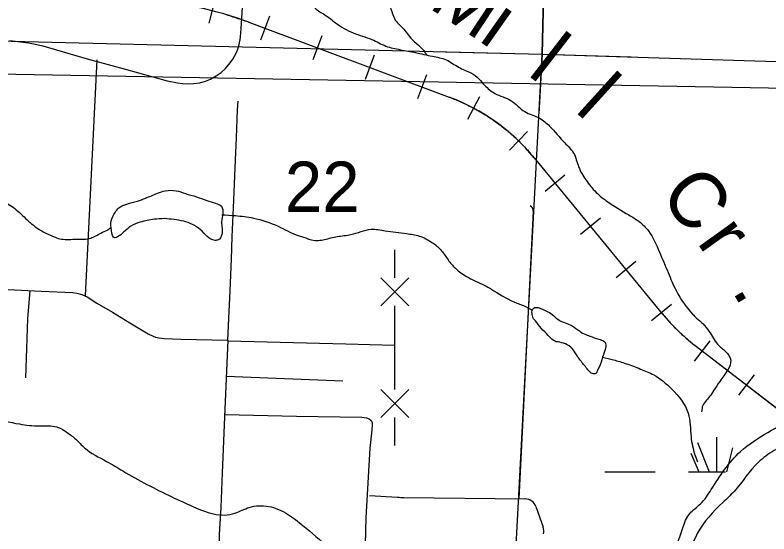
# Model space of a CAD drawing. Extents: x 1219626 to 1426462, y 456797 to 752399.
# Drawn here: x 1327316 to 1334060, y 638144 to 642787 of the extents above; entities that cross this region are included whole.
import ezdxf

# ---------------------------------------------------------------- set-up
doc = ezdxf.new("R2010")
doc.units = 0
for name, color, linetype in [('County Routes Highway Center Lines', 7, 'Continuous'), ('Lakes and Ponds', 7, 'Continuous'), ('Local Roads Improved', 7, 'Continuous'), ('Local Roads Paved', 7, 'Continuous'), ('Masks', 7, 'Continuous'), ('Narrow River Creek and Branch and Slough', 7, 'Continuous'), ('Narrow River Creek and Branch and Slough Text', 7, 'Continuous'), ('Quad Borders', 7, 'Continuous'), ('Railroads', 7, 'Continuous'), ('Section Lines', 7, 'Continuous'), ('Section Numbers', 7, 'Continuous'), ('Swamps', 7, 'Continuous')]:
    doc.layers.add(name, color=color, linetype=linetype)

msp = doc.modelspace()

# ---------------------------------------------------------------- linework, layer by layer
at = {"layer": 'County Routes Highway Center Lines'}
msp.add_lwpolyline([(1327269.2, 642558.3), (1327437, 642536.9), (1327493.8, 642527.7), (1327564.6, 642512.2), (1327960.5, 642393.8), (1328291.3, 642305), (1328676.5, 642199.3), (1328768.2, 642179.9), (1328813.3, 642174.6), (1328868.6, 642171.6), (1328911.3, 642173.1), (1328969, 642181.8), (1329020.5, 642195.9), (1329063.2, 642214.3), (1329113.6, 642242.5), (1329159.2, 642274), (1329199.5, 642308.4), (1329240.7, 642358.4), (1329264.5, 642391.4), (1329293.6, 642445.2), (1329309.1, 642482.1), (1329320.8, 642524.8), (1329327.1, 642554.9), (1329330.5, 642566), (1329333.4, 642592.7), (1329339.7, 642663.6), (1329351.3, 642858.6)], dxfattribs=at)
at = {"layer": 'Lakes and Ponds'}
for points in [[(1337496.8, 643358.7), (1337429, 643264.9), (1337335.2, 643134.4), (1337262.2, 642951.9), (1337173.5, 642738), (1337131.8, 642685.8), (1336725.2, 642425), (1336422.8, 642247.7), (1336244.5, 642121.7), (1336145.4, 641996.5), (1336072.4, 641923.4), (1335957.7, 641850.4), (1335832.6, 641667.8), (1335764.8, 641490.5), (1335698.1, 641245.8), (1335658, 640924.7), (1335603.2, 640640.2), (1335587.6, 640316.8), (1335629.3, 640069.1), (1335665.8, 639949.1), (1335697.1, 639787.4), (1335676.2, 639683.1), (1335551.1, 639484.9), (1335264.3, 639276.2), (1335123.6, 639177.1), (1334925.5, 639119.7), (1334539.7, 639041.5), (1334273.8, 638978.9), (1334106.9, 638890.2), (1333966.2, 638785.9), (1333748.1, 638523.6), (1333648.1, 638426), (1333419.8, 638147.9), (1333325.9, 637908), (1333299.9, 637746.3), (1333378.1, 637600.2), (1333491.3, 637552.1), (1333576.2, 637506.3), (1333696.1, 637428.1), (1333727.4, 637188.1), (1333706.5, 637010.7), (1333654.4, 636781.2), (1333670, 636666.5), (1333774.3, 636520.4), (1333836.9, 636452.6), (1333899.4, 636379.6), (1333935.9, 636207.4), (1333920.3, 636009.2), (1333826.4, 635816.2), (1333779.5, 635596.2), (1333717, 635513.6), (1333587.6, 635343.8), (1333482.4, 635210.2), (1333477.1, 635079.8), (1333461.5, 634876.3), (1333435.4, 634740.7), (1333338.8, 634540.9), (1333258.6, 634436.5), (1333232.1, 634325.7), (1333338.8, 634324.1), (1333466.7, 634292.1), (1333591.8, 634210.9), (1333701.3, 633877.1), (1333664.8, 633715.4), (1333628.3, 633621.5), (1333498, 633556.6), (1333425, 633447), (1333372.9, 633347.9), (1333284.2, 633207.1), (1333294.7, 633026.8), (1333419.1, 632991.3), (1333499.3, 633039.4), (1333675.3, 633089.4), (1333717, 633073.7), (1333847.3, 632880.7), (1333828.3, 632750.4), (1333701.3, 632515.6), (1333563.5, 632348.9), (1333477.1, 632275.6), (1333331.2, 632055), (1333284.2, 631940.2), (1333290.7, 631827), (1333379, 631618.3), (1333451.2, 631465.7), (1333440.6, 631340.3), (1333482.4, 631152.5), (1333482.4, 631079.5), (1333456.3, 630985.6), (1333362.9, 630919.8), (1333310.3, 630923), (1333190.4, 631001.3)], [(1332856.7, 631063.9), (1332789.9, 631132.1), (1332701.7, 631244.5), (1332685.6, 631381), (1332709.7, 631485.3), (1332798, 631565.6), (1332886.2, 631605.8), (1332998.6, 631637.9), (1333119, 631589.7), (1333195.6, 631533.3), (1333183.2, 631621.8), (1333133, 631710.7), (1333117.4, 631862), (1333159.1, 632081.1), (1333273.8, 632265.2), (1333375.8, 632392.6), (1333488.1, 632521.1), (1333633.5, 632672.1), (1333649.2, 632755.5), (1333659.6, 632823.4), (1333623.1, 632891.2), (1333508.4, 632859.9), (1333315.5, 632805.4), (1333180, 632826.3), (1333075.7, 632988), (1333075.7, 633066.2), (1333122.6, 633248.8), (1333153.9, 633316.6), (1333247.7, 633462.7), (1333325.9, 633640), (1333414.6, 633723.5), (1333461.5, 633754.8), (1333498, 633916.5), (1333472, 634025.9), (1333331.2, 634153.5), (1333211.3, 634127.4), (1333112.2, 634137.9), (1333014.6, 634218.6), (1332961, 634328.6), (1332990.6, 634459.4), (1333030.7, 634531.7), (1333038.7, 634612), (1333117.4, 634594.6), (1333180, 634678.1), (1333221.7, 634735.5), (1333284.2, 634865.9), (1333310.3, 635043.2), (1333352, 635236.2), (1333456, 635422.9), (1333571, 635617), (1333670, 635863.1), (1333696.7, 636049.2), (1333732.6, 636249.2), (1333664.6, 636358.6), (1333571, 636457.8), (1333503.2, 636645.6), (1333508.4, 636749.9), (1333544.9, 636963.8), (1333571, 637115.1), (1333581.4, 637287.2), (1333529.3, 637355), (1333456.3, 637381.1), (1333315.5, 637480.2), (1333237.3, 637506.3), (1333164.3, 637615.9), (1333138.3, 637746.3), (1333138.3, 637881.9), (1333237.3, 638059.2), (1333351.7, 638325.7), (1333450, 638415.5), (1333543.9, 638540.7), (1333805.1, 638881.4), (1334049.6, 639051.9), (1334336.3, 639187.6), (1334670, 639250.1), (1335019.3, 639333.6), (1335347.8, 639547.5), (1335499, 639870.9), (1335467.7, 640024.7), (1335431.2, 640337.7), (1335431.2, 640593.3), (1335467.7, 640968.8), (1335514.6, 641250.5), (1335587.6, 641480), (1335676.2, 641709.6), (1335811.2, 641956.5), (1336011.9, 642149.2), (1336284.3, 642356.5), (1336443.6, 642451.1), (1336683.5, 642545), (1336839.9, 642644.1)], [(1328411.1, 641122.1), (1328481.3, 641148.2), (1328589.6, 641192.3), (1328659.8, 641214.4), (1328758.1, 641214.4), (1328840.3, 641190.3), (1328938.6, 641160.2), (1329030.9, 641128.1), (1329109.1, 641104), (1329161.3, 641075.9), (1329163.3, 640935.4), (1329165.3, 640823), (1329133.2, 640774.9), (1329105.1, 640770.9), (1328972.7, 640867.2), (1328824.3, 640941.5), (1328649.8, 640965.5)], [(1328649.8, 640965.5), (1328561.5, 640959.5), (1328435.2, 640933.4), (1328350.9, 640897.3), (1328286.7, 640843.1), (1328232.6, 640801), (1328208.5, 640792.9), (1328178.4, 640859.2), (1328176.4, 640945.5), (1328210.5, 641019.7), (1328244.6, 641061.9), (1328316.8, 641096), (1328411.1, 641122.1)], [(1332157.8, 639864.4), (1332128.9, 639877.9), (1332086.4, 639920.3), (1332022.8, 639984), (1331970.7, 640051.6), (1331951.4, 640074.8), (1331941.7, 640117.2), (1331941.7, 640142.3), (1331966.8, 640169.3), (1331995.8, 640169.3), (1332034.3, 640153.9), (1332082.6, 640132.7), (1332132.7, 640097.9)], [(1332132.7, 640097.9), (1332184.8, 640055.5), (1332223.4, 640038.1), (1332281.3, 640014.9), (1332350.7, 639970.5), (1332408.6, 639933.9), (1332458.7, 639914.6), (1332537.8, 639885.6), (1332584.1, 639868.2), (1332599.5, 639848.9), (1332593.8, 639793), (1332572.5, 639725.4), (1332541.7, 639636.6), (1332520.5, 639594.2), (1332512.7, 639580.7), (1332479.9, 639578.7), (1332449.1, 639603.8), (1332387.4, 639679.1), (1332331.4, 639756.3), (1332287, 639816.1), (1332221.5, 639850.9), (1332157.8, 639864.4)]]:
    msp.add_spline(points, degree=3, dxfattribs=at)
at = {"layer": 'Local Roads Improved'}
for p, q in [((1331951.2, 641033.5), (1331824, 638458)), ((1330714.1, 640436.1), (1330714.1, 640686.1)), ((1330589.1, 640186.1), (1330839.1, 640436.1)), ((1330589.1, 640436.1), (1330839.1, 640186.1)), ((1330714.1, 639436.1), (1330714.1, 640186.1)), ((1330589.1, 639186.1), (1330839.1, 639436.1)), ((1330589.1, 639436.1), (1330839.1, 639186.1)), ((1330714.1, 638936.1), (1330714.1, 639186.1)), ((1330488.1, 638488), (1330738.3, 638472.9)), ((1331974.4, 638390.6), (1332040.1, 638204.7))]:
    msp.add_line(p, q, dxfattribs=at)
for points in [[(1329219.2, 639877.2), (1329192.9, 639260.2), (1329167.9, 638691.5), (1329156.7, 638380.9), (1329140.4, 638138.3), (1329133.5, 637682.3), (1329110.3, 637187.6), (1329078.4, 636599.1), (1329061.2, 636055.4), (1329041.4, 635492.7), (1329021.6, 634953.3), (1329000.1, 634404.4), (1328986.4, 634104.2), (1328980.4, 634068.9), (1328958.8, 634038.8), (1328936.5, 634029.3), (1328885.7, 634029.3), (1328724.8, 634030.2), (1327837, 634027.6), (1327513.5, 634029.3)], [(1329218.9, 639870.7), (1330274.3, 639844.4), (1330711.4, 639834)], [(1330795.3, 638470.9), (1331881.4, 638457.3)]]:
    msp.add_lwpolyline(points, dxfattribs=at)
for centre, radius, start, end in [((1331901.3, 641036), 50, 357.1714, 62.37816), ((1330810.3, 639670.8), 1200, 266.55966, 269.28384), ((1331880.1, 638357.3), 100, 19.44601, 89.28384), ((1331945.8, 638171.4), 100, 344.22182, 19.44601)]:
    msp.add_arc(centre, radius, start, end, dxfattribs=at)
at = {"layer": 'Local Roads Paved'}
for p, q in [((1328047.3, 642385.6), (1327942.9, 640274)), ((1329205.4, 639554.7), (1330247.1, 639515.4))]:
    msp.add_line(p, q, dxfattribs=at)
for points in [[(1329219.2, 639877.2), (1329226.8, 640071.5), (1329238.9, 640320.6), (1329251.4, 640603.2), (1329259.1, 640801.5), (1329274.2, 641130.1), (1329285.3, 641423.1), (1329295.7, 641687.6), (1329306.9, 641939.3), (1329311.6, 642016.7)], [(1326954.2, 640345.9), (1327547.5, 640315.4), (1327833.5, 640302.9), (1327867.9, 640299.5), (1327911.8, 640287), (1327961.3, 640266.4), (1328046.9, 640210), (1328187.1, 640128.7), (1328343.3, 640032.3), (1328505.9, 639935.6), (1328551.5, 639912.3), (1328572.6, 639904.6), (1328603.1, 639898.1), (1328648.7, 639891.7), (1328798.4, 639886.9), (1329219.2, 639877.2)], [(1327446.3, 640320.6), (1327425.3, 640070.6), (1327418, 639803.5), (1327408.9, 639542)], [(1329190.8, 639212.5), (1329834.7, 639199.1), (1330418.8, 639187.9), (1330460.1, 639181.9), (1330484.2, 639173.3), (1330502.3, 639159.5), (1330509.2, 639141.5), (1330510.9, 639114.8), (1330503.2, 639046.8), (1330491.1, 638912.6), (1330455, 638288.9), (1330446.4, 638054), (1330416.3, 637606.6), (1330412, 637534.3), (1330405.9, 637505.1), (1330385.3, 637490.5), (1330363.8, 637483.6), (1329893.2, 637500.8), (1329597.2, 637511.1), (1329126, 637522.2)]]:
    msp.add_lwpolyline(points, dxfattribs=at)
at = {"layer": 'Masks'}
for p, q in [((1332043.9, 642962.3), (1332030.5, 642436.6)), ((1331167.5, 642457.7), (1332030.5, 642436.6)), ((1332030.5, 642436.6), (1332002.5, 641904.4)), ((1332030.5, 642436.6), (1332828.9, 642412))]:
    msp.add_line(p, q, dxfattribs=at)
at = {"layer": 'Narrow River Creek and Branch and Slough'}
for points in [[(1327523.7, 647493.8), (1327491.2, 647422.2), (1327432.6, 647298.4), (1327426.1, 647200.7), (1327452.1, 647031.3), (1327497.7, 646842.4), (1327517.2, 646647), (1327549.8, 646497.2), (1327569.3, 646425.5), (1327601.9, 646373.4), (1327653.9, 646269.2), (1327719, 646112.8), (1327784.1, 645930.4), (1327855.8, 645748), (1327849.3, 645689.4), (1327940.4, 645546.1), (1327973, 645494), (1328018.5, 645448.4), (1328070.6, 645409.3), (1328122.7, 645272.5), (1328187.8, 645155.3), (1328246.4, 645096.6), (1328285.5, 645025), (1328265.9, 644933.8), (1328331, 644829.6), (1328370.1, 644757.9), (1328487.3, 644686.3), (1328598, 644634.1), (1328682.6, 644569), (1328773.7, 644471.3), (1328877.9, 644347.5), (1328923.5, 644236.8), (1328982.1, 644132.6), (1329021.1, 643969.7), (1329053.7, 643859), (1329053.7, 643780.8), (1329086.2, 643702.6), (1329190.4, 643624.5), (1329265.3, 643551.9), (1329382.5, 643428.1), (1329558.3, 643232.7), (1329668.9, 643141.5), (1329786.1, 643069.8), (1329890.3, 642998.2), (1329948.9, 642926.5), (1330001, 642848.4), (1330085.6, 642789.7), (1330183.3, 642718.1), (1330339.5, 642626.9), (1330508.8, 642568.3), (1330632.5, 642509.6), (1330762.7, 642477.1), (1330899.4, 642451), (1331049.2, 642418.4), (1331172.9, 642385.9), (1331283.5, 642320.7), (1331394.2, 642268.6), (1331465.8, 642216.5), (1331517.9, 642157.9), (1331609.1, 642086.2), (1331752.3, 642021.1), (1331876, 641923.4), (1332006.2, 641864.7), (1332097.4, 641793.1), (1332234.1, 641643.3), (1332312.2, 641552.1), (1332357.8, 641428.3), (1332422.9, 641311), (1332514, 641200.3), (1332618.2, 641115.6), (1332807, 640998.4), (1332898.1, 640939.7), (1332982.8, 640855.1), (1333080.4, 640666.2), (1333158.6, 640483.8), (1333230.2, 640320.9), (1333379.9, 640108.5), (1333412.5, 640075.9), (1333471.1, 640023.8), (1333523.2, 639958.7), (1333562.2, 639900), (1333601.3, 639841.4), (1333672.9, 639776.3), (1333718.5, 639698.1), (1333692.4, 639613.4), (1333620.8, 639509.2), (1333568.7, 639431), (1333529.7, 639372.4), (1333464.6, 639281.2), (1333458, 639235.6)], [(1330201.5, 644287.7), (1330270, 644204.7), (1330349.3, 644085.7), (1330425, 643898.2), (1330443, 643790), (1330468.2, 643624.1), (1330504.3, 643375.2), (1330518.7, 643194.9), (1330525.9, 643093.9), (1330572.7, 643011), (1330612.4, 642946), (1330677.3, 642841.4), (1330709.7, 642754.9), (1330792.6, 642661.1), (1330879.1, 642556.5), (1330962, 642480.8), (1330997.2, 642430)], [(1325238.9, 641414.7), (1325315.8, 641400.8), (1325487.3, 641378.2), (1325636.3, 641346.6), (1325816.8, 641328.5), (1325934.1, 641310.5), (1326037.9, 641296.9), (1326128.2, 641315), (1326295.2, 641364.7), (1326471.2, 641369.2), (1326674.3, 641351.1), (1326845.8, 641296.9), (1327035.3, 641206.6), (1327175.2, 641138.9), (1327297.1, 641066.6), (1327409.9, 640967.3), (1327518.2, 640877), (1327617.5, 640822.8), (1327730.4, 640782.2), (1327865.8, 640782.2), (1327992.1, 640791.2), (1328082.4, 640836.3), (1328141.1, 640863.4), (1328171.8, 640885.8)], [(1329164.3, 641000.7), (1329286.8, 640992), (1329447.4, 640970.3), (1329668.7, 640896.5), (1329838, 640818.3), (1329916.1, 640792.3), (1329968.2, 640774.9), (1330085.4, 640779.2), (1330198.2, 640805.3), (1330319.8, 640822.7), (1330502.1, 640870.4), (1330627.9, 640857.4), (1330818.9, 640831.4), (1330931.8, 640809.6), (1331044.6, 640753.2), (1331122.7, 640688), (1331183.5, 640605.5), (1331244.3, 640531.7), (1331344.1, 640453.5), (1331435.2, 640405.8), (1331513.4, 640371), (1331600.2, 640318.9), (1331804.2, 640210.3), (1331899.6, 640171.3), (1331943.4, 640146.9)], [(1332572.2, 639724.5), (1332669.2, 639702.2), (1332782, 639667.5), (1332912.2, 639619.7), (1333029.4, 639567.6), (1333190, 639441.7), (1333337.6, 639224.5), (1333363.6, 639011.8), (1333398.4, 638851.1), (1333420.1, 638790.3)], [(1324055.1, 638887.8), (1324123.7, 638999.2), (1324218, 639093.5), (1324355.1, 639256.5), (1324440.8, 639350.8), (1324526.5, 639436.5), (1324612.2, 639470.8), (1324715, 639470.8), (1324929.3, 639462.3), (1325074.9, 639453.7), (1325246.3, 639479.4), (1325434.9, 639548), (1325640.6, 639599.4), (1325777.7, 639625.2), (1325914.8, 639659.5), (1326129, 639650.9), (1326283.3, 639599.4), (1326463.2, 639556.6), (1326548.9, 639505.1), (1326643.2, 639436.5), (1326711.8, 639350.8), (1326806, 639265), (1326926, 639213.6), (1327097.4, 639179.3), (1327354.5, 639127.8), (1327534.5, 639110.7), (1327688.7, 639102.1), (1327783, 639050.7), (1327860.1, 638990.7), (1327937.2, 638913.5), (1328134.3, 638793.4), (1328280, 638707.7), (1328494.3, 638587.7), (1328717.1, 638476.2), (1328905.6, 638390.4), (1329188.4, 638313.3), (1329282.7, 638330.4), (1329411.2, 638381.9), (1329582.6, 638390.4), (1329754, 638321.9), (1329891.1, 638219), (1330118.3, 638021.7), (1330229.7, 637910.3), (1330358.2, 637798.8), (1330495.3, 637738.8), (1330649.6, 637653), (1330821, 637550.2), (1330906.7, 637464.4), (1330992.4, 637344.4), (1331095.2, 637207.2), (1331172.3, 637087.1), (1331206.6, 636992.8), (1331283.7, 636872.8), (1331378, 636761.3), (1331438, 636658.4), (1331489.4, 636555.5), (1331523.7, 636478.3), (1331532.3, 636418.3), (1331540.8, 636332.6), (1331566.5, 636204), (1331626.5, 636092.5), (1331763.6, 635989.6), (1331969.3, 635912.4)]]:
    msp.add_spline(points, degree=3, dxfattribs=at)
at = {"layer": 'Quad Borders'}
msp.add_line((1340252.6, 642021.5), (1300989.8, 642732), dxfattribs=at)
at = {"layer": 'Railroads'}
for p, q in [((1329104.3, 642937.6), (1329047.9, 642714.6)), ((1329408.4, 642722.1), (1331200.3, 642052.2)), ((1329590.7, 642776.8), (1329510.2, 642561.3)), ((1330059, 642601.7), (1329978.5, 642386.2)), ((1330527.4, 642426.6), (1330446.8, 642211.1)), ((1330995.7, 642251.5), (1330915.2, 642036)), ((1331471.5, 642055.7), (1331363.7, 641852.5)), ((1331900.4, 641743.5), (1331740.7, 641578)), ((1331960.6, 641509), (1333106.7, 640114.4)), ((1332235.7, 641355.4), (1332058, 641209.3)), ((1332553.2, 640969.1), (1332375.5, 640823)), ((1332870.6, 640582.8), (1332692.9, 640436.8)), ((1333188.1, 640196.5), (1333010.4, 640050.5)), ((1333532.8, 639873.3), (1333392.5, 639691)), ((1333399.5, 639830.8), (1335090.4, 638529.3)), ((1333929, 639568.3), (1333788.8, 639386.1))]:
    msp.add_line(p, q, dxfattribs=at)
for points in [[(1329202.8, 642791.1), (1329218.1, 642786.5), (1329233.4, 642781.8), (1329248.7, 642777.1), (1329264, 642772.2), (1329279.2, 642767.3), (1329294.4, 642762.3), (1329309.6, 642757.2), (1329324.7, 642752.1), (1329339.8, 642746.9), (1329354.9, 642741.6), (1329370, 642736.2), (1329385.1, 642730.8), (1329400.1, 642725.2), (1329408.4, 642722.1), (1331200.3, 642052.2), (1331211.5, 642048), (1331222.7, 642043.7), (1331233.9, 642039.3), (1331245, 642034.8), (1331256.1, 642030.3), (1331267.2, 642025.7), (1331278.2, 642021), (1331289.2, 642016.2), (1331300.2, 642011.4), (1331311.2, 642006.5), (1331322.1, 642001.5), (1331333, 641996.5), (1331343.8, 641991.3), (1331354.7, 641986.1), (1331365.4, 641980.9), (1331376.2, 641975.5), (1331386.9, 641970.1), (1331397.6, 641964.6), (1331408.2, 641959.1), (1331418.8, 641953.5), (1331429.4, 641947.8), (1331439.9, 641942), (1331450.4, 641936.2), (1331460.8, 641930.3), (1331471.2, 641924.3), (1331481.6, 641918.2), (1331491.9, 641912.1), (1331502.2, 641905.9), (1331512.5, 641899.7), (1331522.7, 641893.4), (1331532.8, 641887), (1331542.9, 641880.5), (1331553, 641874), (1331563, 641867.4), (1331573, 641860.8), (1331583, 641854.1), (1331592.9, 641847.3), (1331602.7, 641840.4), (1331612.5, 641833.5), (1331622.3, 641826.5), (1331632, 641819.5), (1331641.7, 641812.4), (1331651.3, 641805.2), (1331660.8, 641797.9), (1331670.4, 641790.6), (1331679.8, 641783.3), (1331689.3, 641775.8), (1331698.6, 641768.3), (1331707.9, 641760.8), (1331717.2, 641753.2), (1331726.4, 641745.5), (1331735.6, 641737.8), (1331744.7, 641729.9), (1331753.8, 641722.1), (1331762.8, 641714.2), (1331771.8, 641706.2), (1331780.7, 641698.1), (1331789.5, 641690)], [(1331789.5, 641690), (1331798.3, 641681.9), (1331807.1, 641673.7), (1331815.8, 641665.4), (1331824.4, 641657), (1331833, 641648.7), (1331841.5, 641640.2), (1331850, 641631.7), (1331858.4, 641623.1), (1331866.7, 641614.5), (1331875, 641605.8), (1331883.2, 641597.1), (1331891.4, 641588.3), (1331899.5, 641579.5), (1331907.6, 641570.6), (1331915.6, 641561.7), (1331923.5, 641552.7), (1331931.4, 641543.6), (1331939.2, 641534.5), (1331947, 641525.4), (1331954.7, 641516.2), (1331960.6, 641509), (1333106.7, 640114.4), (1333114.4, 640105.1), (1333122.1, 640095.9), (1333129.8, 640086.8), (1333137.7, 640077.7), (1333145.6, 640068.6), (1333153.5, 640059.7), (1333161.5, 640050.7), (1333169.6, 640041.8), (1333177.7, 640033), (1333185.9, 640024.3), (1333194.2, 640015.5), (1333202.5, 640006.9), (1333210.9, 639998.3), (1333219.3, 639989.7), (1333227.8, 639981.2), (1333236.3, 639972.8), (1333244.9, 639964.4), (1333253.5, 639956.1), (1333262.2, 639947.8), (1333271, 639939.6), (1333279.8, 639931.5), (1333288.7, 639923.4), (1333297.6, 639915.4), (1333306.6, 639907.4), (1333315.6, 639899.5), (1333324.7, 639891.6), (1333333.8, 639883.9), (1333343, 639876.1), (1333352.2, 639868.5), (1333361.5, 639860.9), (1333370.8, 639853.3), (1333380.2, 639845.8), (1333389.6, 639838.4), (1333399.1, 639831.1), (1333399.5, 639830.8), (1335090.4, 638529.3)]]:
    msp.add_lwpolyline(points, dxfattribs=at)
for centre, radius, start, end in [((1328287.8, 639724.8), 3200, 69.50091, 86.56307), ((1330569.9, 640366.2), 1800, 39.41328, 69.50091), ((1334497.4, 641257.2), 1800, 219.41328, 232.41559)]:
    msp.add_arc(centre, radius, start, end, dxfattribs=at)
at = {"layer": 'Section Lines'}
for p, q in [((1332030.5, 642436.6), (1332165.2, 647726.9)), ((1326684.8, 642567.4), (1332030.5, 642436.6)), ((1331751.6, 637130.9), (1332030.5, 642436.6)), ((1332030.5, 642436.6), (1337366.1, 642272.1))]:
    msp.add_line(p, q, dxfattribs=at)
at = {"layer": 'Swamps'}
for p, q in [((1333590.6, 639011.1), (1333590.6, 638700.1)), ((1333421.5, 638962.8), (1333524.5, 638700.1)), ((1333735.6, 638914.4), (1333682, 638700)), ((1333361.1, 638866.1), (1333431.9, 638700.1)), ((1332592, 638700.1), (1333042, 638700.1))]:
    msp.add_line(p, q, dxfattribs=at)
msp.add_lwpolyline([(1333342, 638700.1), (1333672.9, 638700.1)], dxfattribs=at)

# ---------------------------------------------------------------- texts
at = {"layer": 'Narrow River Creek and Branch and Slough Text'}
for s, rotation, p in [('M', 326.58524, (1331005.4, 642858.1)), ('i', 324.81268, (1331452.7, 642563.7)), ('l', 322.23918, (1331891, 642256.1)), ('l', 317.81861, (1332316, 641929.9)), ('C', 309.23055, (1333070.1, 641170.8)), ('r', 305.60695, (1333408.8, 640755.9)), ('.', 300.05994, (1333725, 640323))]:
    msp.add_text(s, height=500, rotation=rotation, dxfattribs=at).set_placement(p)
at = {"layer": 'Section Numbers'}
msp.add_text('22', height=450, rotation=359.99983, dxfattribs=at).set_placement((1329729, 641025.7))

doc.saveas('drawing.dxf')
